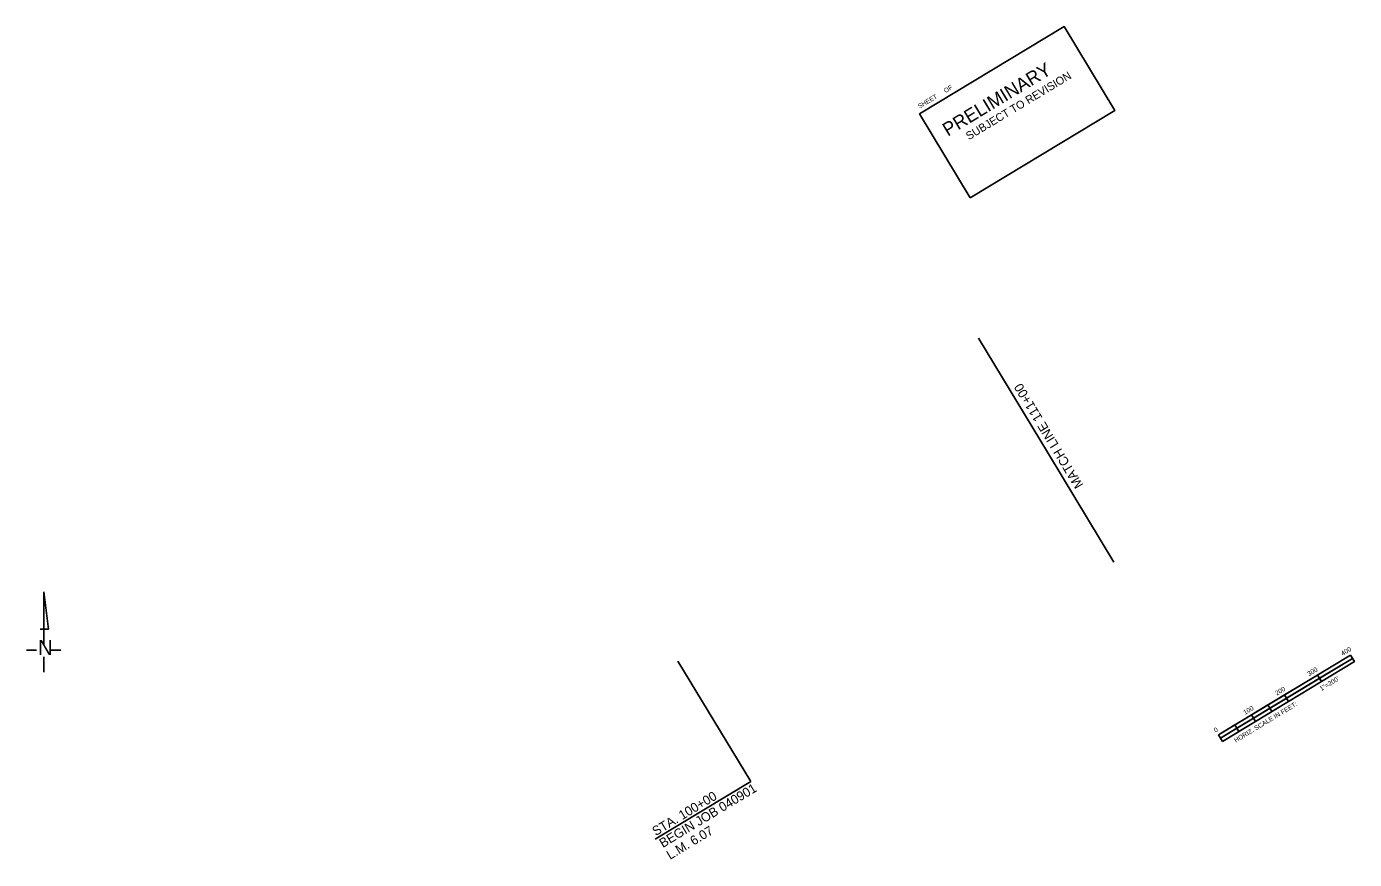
# Model space of a CAD drawing. Extents: x 627405 to 651306, y 367647 to 373430.
# Drawn here: x 627405 to 630847, y 367647 to 369807 of the extents above; entities that cross this region are included whole.
import ezdxf

# ---------------------------------------------------------------- set-up
doc = ezdxf.new("R2010")
doc.units = 0
for name, color, linetype in [('R_Border Prem', 7, 'Continuous'), ('R_Border_N Arrow', 7, 'Continuous'), ('R_Border_Scale', 7, 'Continuous'), ('R_Draft', 7, 'Continuous'), ('R_No Plot', 7, 'Continuous'), ('R_Title_Text', 7, 'Continuous')]:
    doc.layers.add(name, color=color, linetype=linetype)

msp = doc.modelspace()

# ---------------------------------------------------------------- linework, layer by layer
at = {"layer": 'R_Border_N Arrow'}
for p, q in [((627449.3, 368340.8), (627461.4, 368243.8)), ((627449.3, 368205.2), (627449.3, 368340.8)), ((627439.9, 368244.6), (627461.5, 368244.6)), ((627404.7, 368189.3), (627430.4, 368189.3)), ((627466.4, 368189.3), (627493.9, 368189.3)), ((627449.3, 368132.5), (627449.3, 368172.4))]:
    msp.add_line(p, q, dxfattribs=at)
at = {"layer": 'R_Border_Scale'}
for p, q in [((630494, 367970), (630836.3, 368177)), ((630499.2, 367961.4), (630841.5, 368168.4)), ((630504.4, 367952.9), (630846.7, 368159.9)), ((630846.7, 368159.9), (630836.3, 368177)), ((630761.1, 368108.1), (630750.7, 368125.2)), ((630494, 367970), (630665.2, 368073.5)), ((630632.7, 368030.5), (630622.4, 368047.6)), ((630675.5, 368056.4), (630665.2, 368073.5)), ((630590, 368004.6), (630579.6, 368021.7)), ((630547.2, 367978.8), (630536.8, 367995.9)), ((630504.4, 367952.9), (630494, 367970))]:
    msp.add_line(p, q, dxfattribs=at)
for points in [[(630761.1, 368108.1), (630846.7, 368159.9), (630841.5, 368168.4), (630755.9, 368116.7)], [(630670.3, 368064.9), (630755.9, 368116.7), (630750.7, 368125.2), (630665.2, 368073.5)], [(630579.6, 368021.7), (630622.4, 368047.6), (630627.6, 368039.1), (630584.8, 368013.2)], [(630627.6, 368039.1), (630670.3, 368064.9), (630675.5, 368056.4), (630632.7, 368030.5)], [(630542, 367987.3), (630584.8, 368013.2), (630590, 368004.6), (630547.2, 367978.8)], [(630494, 367970), (630536.8, 367995.9), (630542, 367987.3), (630499.2, 367961.4)]]:
    msp.add_lwpolyline(points, close=True, dxfattribs=at)
at = {"layer": 'R_Draft'}
for p, q in [((629093, 368161.6), (629282, 367849.1)), ((629282, 367849.1), (629033.9, 367699.1))]:
    msp.add_line(p, q, dxfattribs=at)
at = {"layer": 'R_No Plot'}
msp.add_lwpolyline([(629850.6, 369363), (630225.6, 369589.9), (630094.1, 369807.3), (629719.1, 369580.5)], close=True, dxfattribs=at)
at = {"layer": 'R_Title_Text'}
for p, q in [((629093, 368161.6), (629282, 367849.1)), ((629282, 367849.1), (629033.9, 367699.1))]:
    msp.add_line(p, q, dxfattribs=at)
msp.add_lwpolyline([(630223.4, 368418), (630053.4, 368699.2), (629872.3, 368998.7)], dxfattribs=at)

# ---------------------------------------------------------------- texts
at = {"layer": 'R_Border Prem'}
for s, height, p in [('PRELIMINARY', 35, (629792.6, 369521.5)), ('SUBJECT TO REVISION', 20.751, (629847.3, 369512.2))]:
    msp.add_text(s, height=height, rotation=31.1638, dxfattribs=at).set_placement(p)
at = {"layer": 'R_Border_N Arrow'}
msp.add_text('N', height=38.8, rotation=360, dxfattribs=at).set_placement((627434.6, 368177.3))
at = {"layer": 'R_Border_Scale'}
for s, p in [('400', (630816.3, 368174.9)), ('300', (630729, 368122.1)), ('1"=200\'', (630760.9, 368083.5)), ('200', (630645.4, 368071.6)), ('HORIZ. SCALE IN FEET:', (630539.3, 367949.5)), ('100', (630563.1, 368021.8)), ('0', (630486.7, 367975.6))]:
    msp.add_text(s, height=12, rotation=31.1637, dxfattribs=at).set_placement(p)
at = {"layer": 'R_Draft'}
for s, p in [('BEGIN JOB 040901', (629054.1, 367676.3)), ('STA. 100+00', (629035.5, 367707.1)), ('L.M. 6.07', (629072.7, 367645.5))]:
    msp.add_text(s, height=24, rotation=31.1638, dxfattribs=at).set_placement(p)
at = {"layer": 'R_No Plot'}
for s, p in [('SHEET', (629719.5, 369593.9)), ('OF', (629786.7, 369634.5))]:
    msp.add_text(s, height=12, rotation=31.1638, dxfattribs=at).set_placement(p)
at = {"layer": 'R_Title_Text'}
for s, rotation, p in [('MATCH LINE 111+00', 121.1638, (630144.5, 368618.1)), ('BEGIN JOB 040901', 31.1638, (629054.1, 367676.3)), ('STA. 100+00', 31.1638, (629035.5, 367707.1)), ('L.M. 6.07', 31.1638, (629072.7, 367645.5))]:
    msp.add_text(s, height=24, rotation=rotation, dxfattribs=at).set_placement(p)

doc.saveas('drawing.dxf')
